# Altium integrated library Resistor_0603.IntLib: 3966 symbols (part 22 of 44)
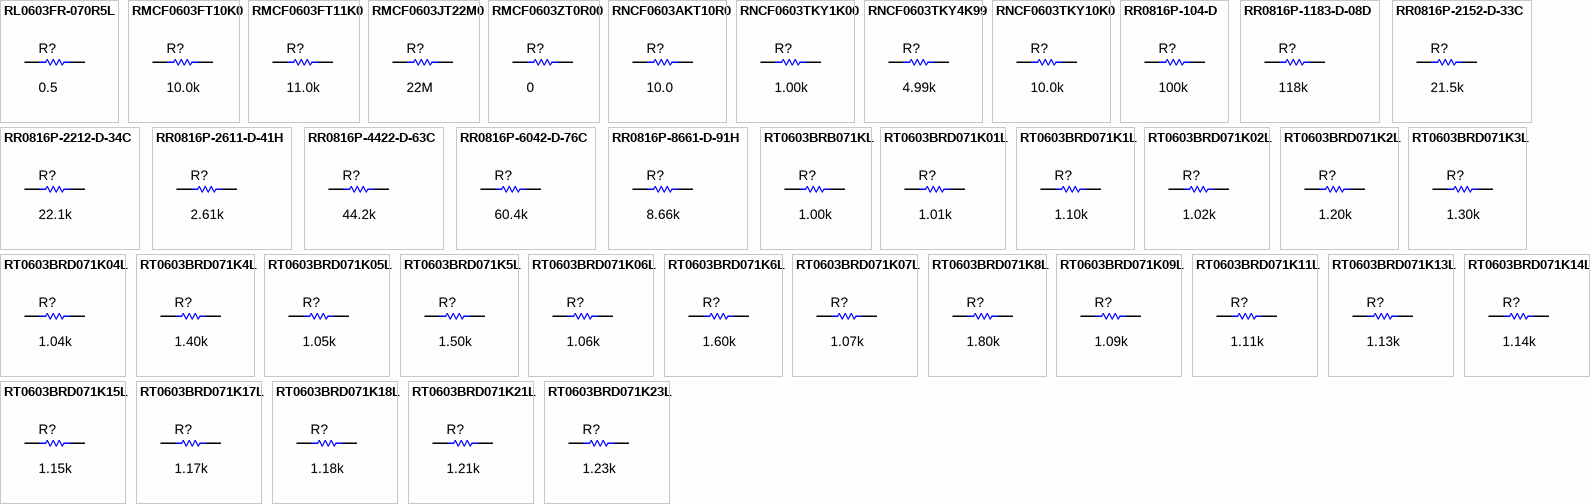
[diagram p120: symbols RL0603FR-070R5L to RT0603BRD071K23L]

## RR0816P-8661-D-91H
designator R?  ValueDisplayed: 8.66k  (hidden comment: RR0816P-8661-D-91H)
RES, 8.66 k, 0.5%, 0.0625 W, 0603; Manufacturer: Susumu Co Ltd; CompType: Resistor; Value: 8.66k; Res_ohm: 8660; Value_Code: 8k66; Tolerance_%: 0.5; Power_W: 0.0625; VDC_V: 75; TempCo: 25 ppm/C; SizeArea_mm2: 1.3175; SizeX_mm: 1.55; SizeY_mm: 0.85; EIA_Code: E192; U/M: EA; AEC Category: Q200; AEC Qualified: N
signal-integrity model Resistor
simulation model Resistor
footprint 0603_HR
pins: 1, 2

## RT0603BRB071KL
designator R?  ValueDisplayed: 1.00k  (hidden comment: RT0603BRB071KL)
RES, 1.00 k, 0.1%, 0.1 W, 0603; Manufacturer: Yageo America; CompType: Resistor; Value: 1.00k; Res_ohm: 1000; Value_Code: 1k00; Tolerance_%: 0.1; Value2: 0.1W; VDC_V: 75; TempCo: 10 ppm/C; SizeArea_mm2: 1.28; SizeX_mm: 1.6; SizeY_mm: 0.8; SizeZ_mm: 1; EIA_Code: E192; U/M: EA; AEC Category: Q200; AEC Qualified: N; Green_Lifecycle: Active; Green_REACh: Passed
signal-integrity model Resistor
simulation model Resistor
footprint 0603
footprint 0603M
footprint 0603L
footprint 0603_HV
footprint 0603S
pins: 1, 2

## RT0603BRD071K01L
designator R?  ValueDisplayed: 1.01k  (hidden comment: RT0603BRD071K01L)
RES, 1.01 k, 0.1%, 0.1 W, 0603; Manufacturer: Yageo America; CompType: Resistor; Value: 1.01k; Res_ohm: 1010; Value_Code: 1k01; Tolerance_%: 0.1; Value2: 0.1W; VDC_V: 75; TempCo: 25 ppm/C; SizeArea_mm2: 1.28; SizeX_mm: 1.6; SizeY_mm: 0.8; SizeZ_mm: 1; EIA_Code: E192; U/M: EA; AEC Category: Q200
signal-integrity model Resistor
simulation model Resistor
footprint 0603
footprint 0603M
footprint 0603L
footprint 0603_HV
footprint 0603S
pins: 1, 2

## RT0603BRD071K1L
designator R?  ValueDisplayed: 1.10k  (hidden comment: RT0603BRD071K1L)
RES, 1.10 k, 0.1%, 0.1 W, 0603; Manufacturer: Yageo America; CompType: Resistor; Value: 1.10k; Res_ohm: 1100; Value_Code: 1k10; Tolerance_%: 0.1; Value2: 0.1W; VDC_V: 75; TempCo: 25 ppm/C; SizeArea_mm2: 1.28; SizeX_mm: 1.6; SizeY_mm: 0.8; SizeZ_mm: 1; EIA_Code: E192; U/M: EA; AEC Category: Q200
signal-integrity model Resistor
simulation model Resistor
footprint 0603
footprint 0603M
footprint 0603L
footprint 0603_HV
footprint 0603S
pins: 1, 2

## RT0603BRD071K02L
designator R?  ValueDisplayed: 1.02k  (hidden comment: RT0603BRD071K02L)
RES, 1.02 k, 0.1%, 0.1 W, 0603; Manufacturer: Yageo America; CompType: Resistor; Value: 1.02k; Res_ohm: 1020; Value_Code: 1k02; Tolerance_%: 0.1; Value2: 0.1W; VDC_V: 75; TempCo: 25 ppm/C; SizeArea_mm2: 1.28; SizeX_mm: 1.6; SizeY_mm: 0.8; SizeZ_mm: 1; EIA_Code: E192; U/M: EA; AEC Category: Q200
signal-integrity model Resistor
simulation model Resistor
footprint 0603
footprint 0603M
footprint 0603L
footprint 0603_HV
footprint 0603S
pins: 1, 2

## RT0603BRD071K2L
designator R?  ValueDisplayed: 1.20k  (hidden comment: RT0603BRD071K2L)
RES, 1.20 k, 0.1%, 0.1 W, 0603; Manufacturer: Yageo America; CompType: Resistor; Value: 1.20k; Res_ohm: 1200; Value_Code: 1k20; Tolerance_%: 0.1; Value2: 0.1W; VDC_V: 75; TempCo: 25 ppm/C; SizeArea_mm2: 1.28; SizeX_mm: 1.6; SizeY_mm: 0.8; SizeZ_mm: 1; EIA_Code: E192; U/M: EA; AEC Category: Q200; Green_Lifecycle: Active; Green_REACh: Passed
signal-integrity model Resistor
simulation model Resistor
footprint 0603
footprint 0603M
footprint 0603L
footprint 0603_HV
footprint 0603S
pins: 1, 2

## RT0603BRD071K3L
designator R?  ValueDisplayed: 1.30k  (hidden comment: RT0603BRD071K3L)
RES, 1.30 k, 0.1%, 0.1 W, 0603; Manufacturer: Yageo America; CompType: Resistor; Value: 1.30k; Res_ohm: 1300; Value_Code: 1k30; Tolerance_%: 0.1; Value2: 0.1W; VDC_V: 75; TempCo: 25 ppm/C; SizeArea_mm2: 1.28; SizeX_mm: 1.6; SizeY_mm: 0.8; SizeZ_mm: 1; EIA_Code: E192; U/M: EA; AEC Category: Q200
signal-integrity model Resistor
simulation model Resistor
footprint 0603
footprint 0603M
footprint 0603L
footprint 0603_HV
footprint 0603S
pins: 1, 2

## RT0603BRD071K04L
designator R?  ValueDisplayed: 1.04k  (hidden comment: RT0603BRD071K04L)
RES, 1.04 k, 0.1%, 0.1 W, 0603; Manufacturer: Yageo America; CompType: Resistor; Value: 1.04k; Res_ohm: 1040; Value_Code: 1k04; Tolerance_%: 0.1; Value2: 0.1W; VDC_V: 75; TempCo: 25 ppm/C; SizeArea_mm2: 1.28; SizeX_mm: 1.6; SizeY_mm: 0.8; SizeZ_mm: 1; EIA_Code: E192; U/M: EA; AEC Category: Q200
signal-integrity model Resistor
simulation model Resistor
footprint 0603
footprint 0603M
footprint 0603L
footprint 0603_HV
footprint 0603S
pins: 1, 2

## RT0603BRD071K4L
designator R?  ValueDisplayed: 1.40k  (hidden comment: RT0603BRD071K4L)
RES, 1.40 k, 0.1%, 0.1 W, 0603; Manufacturer: Yageo America; CompType: Resistor; Value: 1.40k; Res_ohm: 1400; Value_Code: 1k40; Tolerance_%: 0.1; Value2: 0.1W; VDC_V: 75; TempCo: 25 ppm/C; SizeArea_mm2: 1.28; SizeX_mm: 1.6; SizeY_mm: 0.8; SizeZ_mm: 1; EIA_Code: E192; U/M: EA; AEC Category: Q200
signal-integrity model Resistor
simulation model Resistor
footprint 0603
footprint 0603M
footprint 0603L
footprint 0603_HV
footprint 0603S
pins: 1, 2

## RT0603BRD071K05L
designator R?  ValueDisplayed: 1.05k  (hidden comment: RT0603BRD071K05L)
RES, 1.05 k, 0.1%, 0.1 W, 0603; Manufacturer: Yageo America; CompType: Resistor; Value: 1.05k; Res_ohm: 1050; Value_Code: 1k05; Tolerance_%: 0.1; Value2: 0.1W; VDC_V: 75; TempCo: 25 ppm/C; SizeArea_mm2: 1.28; SizeX_mm: 1.6; SizeY_mm: 0.8; SizeZ_mm: 1; EIA_Code: E192; U/M: EA; AEC Category: Q200
signal-integrity model Resistor
simulation model Resistor
footprint 0603
footprint 0603M
footprint 0603L
footprint 0603_HV
footprint 0603S
pins: 1, 2

## RT0603BRD071K5L
designator R?  ValueDisplayed: 1.50k  (hidden comment: RT0603BRD071K5L)
RES, 1.50 k, 0.1%, 0.1 W, 0603; Manufacturer: Yageo America; CompType: Resistor; Value: 1.50k; Res_ohm: 1500; Value_Code: 1k50; Tolerance_%: 0.1; Value2: 0.1W; VDC_V: 75; TempCo: 25 ppm/C; SizeArea_mm2: 1.28; SizeX_mm: 1.6; SizeY_mm: 0.8; SizeZ_mm: 1; EIA_Code: E192; U/M: EA; AEC Category: Q200
signal-integrity model Resistor
simulation model Resistor
footprint 0603
footprint 0603M
footprint 0603L
footprint 0603_HV
footprint 0603S
pins: 1, 2

## RT0603BRD071K06L
designator R?  ValueDisplayed: 1.06k  (hidden comment: RT0603BRD071K06L)
RES, 1.06 k, 0.1%, 0.1 W, 0603; Manufacturer: Yageo America; CompType: Resistor; Value: 1.06k; Res_ohm: 1060; Value_Code: 1k06; Tolerance_%: 0.1; Value2: 0.1W; VDC_V: 75; TempCo: 25 ppm/C; SizeArea_mm2: 1.28; SizeX_mm: 1.6; SizeY_mm: 0.8; SizeZ_mm: 1; EIA_Code: E192; U/M: EA; AEC Category: Q200
signal-integrity model Resistor
simulation model Resistor
footprint 0603
footprint 0603M
footprint 0603L
footprint 0603_HV
footprint 0603S
pins: 1, 2

## RT0603BRD071K6L
designator R?  ValueDisplayed: 1.60k  (hidden comment: RT0603BRD071K6L)
RES, 1.60 k, 0.1%, 0.1 W, 0603; Manufacturer: Yageo America; CompType: Resistor; Value: 1.60k; Res_ohm: 1600; Value_Code: 1k60; Tolerance_%: 0.1; Value2: 0.1W; VDC_V: 75; TempCo: 25 ppm/C; SizeArea_mm2: 1.28; SizeX_mm: 1.6; SizeY_mm: 0.8; SizeZ_mm: 1; EIA_Code: E192; U/M: EA; AEC Category: Q200
signal-integrity model Resistor
simulation model Resistor
footprint 0603
footprint 0603M
footprint 0603L
footprint 0603_HV
footprint 0603S
pins: 1, 2

## RT0603BRD071K07L
designator R?  ValueDisplayed: 1.07k  (hidden comment: RT0603BRD071K07L)
RES, 1.07 k, 0.1%, 0.1 W, 0603; Manufacturer: Yageo America; CompType: Resistor; Value: 1.07k; Res_ohm: 1070; Value_Code: 1k07; Tolerance_%: 0.1; Value2: 0.1W; VDC_V: 75; TempCo: 25 ppm/C; SizeArea_mm2: 1.28; SizeX_mm: 1.6; SizeY_mm: 0.8; SizeZ_mm: 1; EIA_Code: E192; U/M: EA; AEC Category: Q200
signal-integrity model Resistor
simulation model Resistor
footprint 0603
footprint 0603M
footprint 0603L
footprint 0603_HV
footprint 0603S
pins: 1, 2

## RT0603BRD071K8L
designator R?  ValueDisplayed: 1.80k  (hidden comment: RT0603BRD071K8L)
RES, 1.80 k, 0.1%, 0.1 W, 0603; Manufacturer: Yageo America; CompType: Resistor; Value: 1.80k; Res_ohm: 1800; Value_Code: 1k80; Tolerance_%: 0.1; Value2: 0.1W; VDC_V: 75; TempCo: 25 ppm/C; SizeArea_mm2: 1.28; SizeX_mm: 1.6; SizeY_mm: 0.8; SizeZ_mm: 1; EIA_Code: E192; U/M: EA; AEC Category: Q200; Green_Lifecycle: Active; Green_REACh: Passed
signal-integrity model Resistor
simulation model Resistor
footprint 0603
footprint 0603M
footprint 0603L
footprint 0603_HV
footprint 0603S
pins: 1, 2

## RT0603BRD071K09L
designator R?  ValueDisplayed: 1.09k  (hidden comment: RT0603BRD071K09L)
RES, 1.09 k, 0.1%, 0.1 W, 0603; Manufacturer: Yageo America; CompType: Resistor; Value: 1.09k; Res_ohm: 1090; Value_Code: 1k09; Tolerance_%: 0.1; Value2: 0.1W; VDC_V: 75; TempCo: 25 ppm/C; SizeArea_mm2: 1.28; SizeX_mm: 1.6; SizeY_mm: 0.8; SizeZ_mm: 1; EIA_Code: E192; U/M: EA; AEC Category: Q200
signal-integrity model Resistor
simulation model Resistor
footprint 0603
footprint 0603M
footprint 0603L
footprint 0603_HV
footprint 0603S
pins: 1, 2

## RT0603BRD071K11L
designator R?  ValueDisplayed: 1.11k  (hidden comment: RT0603BRD071K11L)
RES, 1.11 k, 0.1%, 0.1 W, 0603; Manufacturer: Yageo America; CompType: Resistor; Value: 1.11k; Res_ohm: 1110; Value_Code: 1k11; Tolerance_%: 0.1; Value2: 0.1W; VDC_V: 75; TempCo: 25 ppm/C; SizeArea_mm2: 1.28; SizeX_mm: 1.6; SizeY_mm: 0.8; SizeZ_mm: 1; EIA_Code: E192; U/M: EA; AEC Category: Q200
signal-integrity model Resistor
simulation model Resistor
footprint 0603
footprint 0603M
footprint 0603L
footprint 0603_HV
footprint 0603S
pins: 1, 2

## RT0603BRD071K13L
designator R?  ValueDisplayed: 1.13k  (hidden comment: RT0603BRD071K13L)
RES, 1.13 k, 0.1%, 0.1 W, 0603; Manufacturer: Yageo America; CompType: Resistor; Value: 1.13k; Res_ohm: 1130; Value_Code: 1k13; Tolerance_%: 0.1; Value2: 0.1W; VDC_V: 75; TempCo: 25 ppm/C; SizeArea_mm2: 1.28; SizeX_mm: 1.6; SizeY_mm: 0.8; SizeZ_mm: 1; EIA_Code: E192; U/M: EA; AEC Category: Q200
signal-integrity model Resistor
simulation model Resistor
footprint 0603
footprint 0603M
footprint 0603L
footprint 0603_HV
footprint 0603S
pins: 1, 2

## RT0603BRD071K14L
designator R?  ValueDisplayed: 1.14k  (hidden comment: RT0603BRD071K14L)
RES, 1.14 k, 0.1%, 0.1 W, 0603; Manufacturer: Yageo America; CompType: Resistor; Value: 1.14k; Res_ohm: 1140; Value_Code: 1k14; Tolerance_%: 0.1; Value2: 0.1W; VDC_V: 75; TempCo: 25 ppm/C; SizeArea_mm2: 1.28; SizeX_mm: 1.6; SizeY_mm: 0.8; SizeZ_mm: 1; EIA_Code: E192; U/M: EA; AEC Category: Q200
signal-integrity model Resistor
simulation model Resistor
footprint 0603
footprint 0603M
footprint 0603L
footprint 0603_HV
footprint 0603S
pins: 1, 2

## RT0603BRD071K15L
designator R?  ValueDisplayed: 1.15k  (hidden comment: RT0603BRD071K15L)
RES, 1.15 k, 0.1%, 0.1 W, 0603; Manufacturer: Yageo America; CompType: Resistor; Value: 1.15k; Res_ohm: 1150; Value_Code: 1k15; Tolerance_%: 0.1; Value2: 0.1W; VDC_V: 75; TempCo: 25 ppm/C; SizeArea_mm2: 1.28; SizeX_mm: 1.6; SizeY_mm: 0.8; SizeZ_mm: 1; EIA_Code: E192; U/M: EA; AEC Category: Q200
signal-integrity model Resistor
simulation model Resistor
footprint 0603
footprint 0603M
footprint 0603L
footprint 0603_HV
footprint 0603S
pins: 1, 2

## RT0603BRD071K17L
designator R?  ValueDisplayed: 1.17k  (hidden comment: RT0603BRD071K17L)
RES, 1.17 k, 0.1%, 0.1 W, 0603; Manufacturer: Yageo America; CompType: Resistor; Value: 1.17k; Res_ohm: 1170; Value_Code: 1k17; Tolerance_%: 0.1; Value2: 0.1W; VDC_V: 75; TempCo: 25 ppm/C; SizeArea_mm2: 1.28; SizeX_mm: 1.6; SizeY_mm: 0.8; SizeZ_mm: 1; EIA_Code: E192; U/M: EA; AEC Category: Q200
signal-integrity model Resistor
simulation model Resistor
footprint 0603
footprint 0603M
footprint 0603L
footprint 0603_HV
footprint 0603S
pins: 1, 2

## RT0603BRD071K18L
designator R?  ValueDisplayed: 1.18k  (hidden comment: RT0603BRD071K18L)
RES, 1.18 k, 0.1%, 0.1 W, 0603; Manufacturer: Yageo America; CompType: Resistor; Value: 1.18k; Res_ohm: 1180; Value_Code: 1k18; Tolerance_%: 0.1; Value2: 0.1W; VDC_V: 75; TempCo: 25 ppm/C; SizeArea_mm2: 1.28; SizeX_mm: 1.6; SizeY_mm: 0.8; SizeZ_mm: 1; EIA_Code: E192; U/M: EA; AEC Category: Q200
signal-integrity model Resistor
simulation model Resistor
footprint 0603
footprint 0603M
footprint 0603L
footprint 0603_HV
footprint 0603S
pins: 1, 2

## RT0603BRD071K21L
designator R?  ValueDisplayed: 1.21k  (hidden comment: RT0603BRD071K21L)
RES, 1.21 k, 0.1%, 0.1 W, 0603; Manufacturer: Yageo America; CompType: Resistor; Value: 1.21k; Res_ohm: 1210; Value_Code: 1k21; Tolerance_%: 0.1; Value2: 0.1W; VDC_V: 75; TempCo: 25 ppm/C; SizeArea_mm2: 1.28; SizeX_mm: 1.6; SizeY_mm: 0.8; SizeZ_mm: 1; EIA_Code: E192; U/M: EA; AEC Category: Q200
signal-integrity model Resistor
simulation model Resistor
footprint 0603
footprint 0603M
footprint 0603L
footprint 0603_HV
footprint 0603S
pins: 1, 2

## RT0603BRD071K23L
designator R?  ValueDisplayed: 1.23k  (hidden comment: RT0603BRD071K23L)
RES, 1.23 k, 0.1%, 0.1 W, 0603; Manufacturer: Yageo America; CompType: Resistor; Value: 1.23k; Res_ohm: 1230; Value_Code: 1k23; Tolerance_%: 0.1; Value2: 0.1W; VDC_V: 75; TempCo: 25 ppm/C; SizeArea_mm2: 1.28; SizeX_mm: 1.6; SizeY_mm: 0.8; SizeZ_mm: 1; EIA_Code: E192; U/M: EA; AEC Category: Q200
signal-integrity model Resistor
simulation model Resistor
footprint 0603
footprint 0603M
footprint 0603L
footprint 0603_HV
footprint 0603S
pins: 1, 2

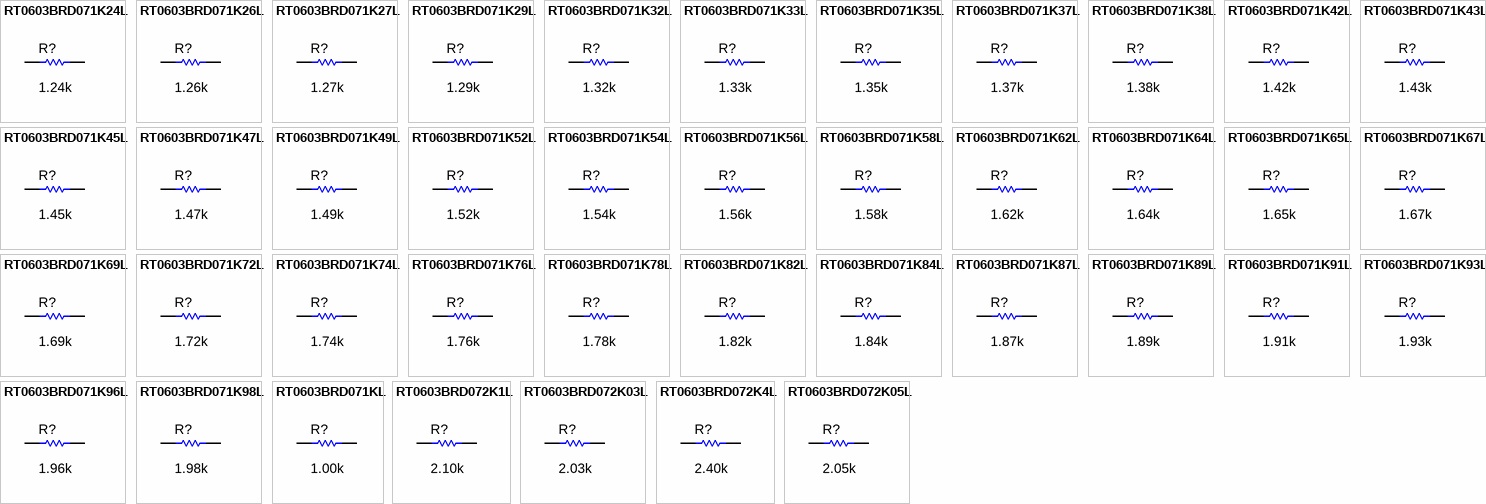
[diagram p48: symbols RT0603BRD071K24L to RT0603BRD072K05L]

## RT0603BRD071K24L
designator R?  ValueDisplayed: 1.24k  (hidden comment: RT0603BRD071K24L)
RES, 1.24 k, 0.1%, 0.1 W, 0603; Manufacturer: Yageo America; CompType: Resistor; Value: 1.24k; Res_ohm: 1240; Value_Code: 1k24; Tolerance_%: 0.1; Value2: 0.1W; VDC_V: 75; TempCo: 25 ppm/C; SizeArea_mm2: 1.28; SizeX_mm: 1.6; SizeY_mm: 0.8; SizeZ_mm: 1; EIA_Code: E192; U/M: EA; AEC Category: Q200
signal-integrity model Resistor
simulation model Resistor
footprint 0603
footprint 0603M
footprint 0603L
footprint 0603_HV
footprint 0603S
pins: 1, 2

## RT0603BRD071K26L
designator R?  ValueDisplayed: 1.26k  (hidden comment: RT0603BRD071K26L)
RES, 1.26 k, 0.1%, 0.1 W, 0603; Manufacturer: Yageo America; CompType: Resistor; Value: 1.26k; Res_ohm: 1260; Value_Code: 1k26; Tolerance_%: 0.1; Value2: 0.1W; VDC_V: 75; TempCo: 25 ppm/C; SizeArea_mm2: 1.28; SizeX_mm: 1.6; SizeY_mm: 0.8; SizeZ_mm: 1; EIA_Code: E192; U/M: EA; AEC Category: Q200
signal-integrity model Resistor
simulation model Resistor
footprint 0603
footprint 0603M
footprint 0603L
footprint 0603_HV
footprint 0603S
pins: 1, 2

## RT0603BRD071K27L
designator R?  ValueDisplayed: 1.27k  (hidden comment: RT0603BRD071K27L)
RES, 1.27 k, 0.1%, 0.1 W, 0603; Manufacturer: Yageo America; CompType: Resistor; Value: 1.27k; Res_ohm: 1270; Value_Code: 1k27; Tolerance_%: 0.1; Value2: 0.1W; VDC_V: 75; TempCo: 25 ppm/C; SizeArea_mm2: 1.28; SizeX_mm: 1.6; SizeY_mm: 0.8; SizeZ_mm: 1; EIA_Code: E192; U/M: EA; AEC Category: Q200
signal-integrity model Resistor
simulation model Resistor
footprint 0603
footprint 0603M
footprint 0603L
footprint 0603_HV
footprint 0603S
pins: 1, 2

## RT0603BRD071K29L
designator R?  ValueDisplayed: 1.29k  (hidden comment: RT0603BRD071K29L)
RES, 1.29 k, 0.1%, 0.1 W, 0603; Manufacturer: Yageo America; CompType: Resistor; Value: 1.29k; Res_ohm: 1290; Value_Code: 1k29; Tolerance_%: 0.1; Value2: 0.1W; VDC_V: 75; TempCo: 25 ppm/C; SizeArea_mm2: 1.28; SizeX_mm: 1.6; SizeY_mm: 0.8; SizeZ_mm: 1; EIA_Code: E192; U/M: EA; AEC Category: Q200
signal-integrity model Resistor
simulation model Resistor
footprint 0603
footprint 0603M
footprint 0603L
footprint 0603_HV
footprint 0603S
pins: 1, 2

## RT0603BRD071K32L
designator R?  ValueDisplayed: 1.32k  (hidden comment: RT0603BRD071K32L)
RES, 1.32 k, 0.1%, 0.1 W, 0603; Manufacturer: Yageo America; CompType: Resistor; Value: 1.32k; Res_ohm: 1320; Value_Code: 1k32; Tolerance_%: 0.1; Value2: 0.1W; VDC_V: 75; TempCo: 25 ppm/C; SizeArea_mm2: 1.28; SizeX_mm: 1.6; SizeY_mm: 0.8; SizeZ_mm: 1; EIA_Code: E192; U/M: EA; AEC Category: Q200
signal-integrity model Resistor
simulation model Resistor
footprint 0603
footprint 0603M
footprint 0603L
footprint 0603_HV
footprint 0603S
pins: 1, 2

## RT0603BRD071K33L
designator R?  ValueDisplayed: 1.33k  (hidden comment: RT0603BRD071K33L)
RES, 1.33 k, 0.1%, 0.1 W, 0603; Manufacturer: Yageo America; CompType: Resistor; Value: 1.33k; Res_ohm: 1330; Value_Code: 1k33; Tolerance_%: 0.1; Value2: 0.1W; VDC_V: 75; TempCo: 25 ppm/C; SizeArea_mm2: 1.28; SizeX_mm: 1.6; SizeY_mm: 0.8; SizeZ_mm: 1; EIA_Code: E192; U/M: EA; AEC Category: Q200
signal-integrity model Resistor
simulation model Resistor
footprint 0603
footprint 0603M
footprint 0603L
footprint 0603_HV
footprint 0603S
pins: 1, 2

## RT0603BRD071K35L
designator R?  ValueDisplayed: 1.35k  (hidden comment: RT0603BRD071K35L)
RES, 1.35 k, 0.1%, 0.1 W, 0603; Manufacturer: Yageo America; CompType: Resistor; Value: 1.35k; Res_ohm: 1350; Value_Code: 1k35; Tolerance_%: 0.1; Value2: 0.1W; VDC_V: 75; TempCo: 25 ppm/C; SizeArea_mm2: 1.28; SizeX_mm: 1.6; SizeY_mm: 0.8; SizeZ_mm: 1; EIA_Code: E192; U/M: EA; AEC Category: Q200
signal-integrity model Resistor
simulation model Resistor
footprint 0603
footprint 0603M
footprint 0603L
footprint 0603_HV
footprint 0603S
pins: 1, 2

## RT0603BRD071K37L
designator R?  ValueDisplayed: 1.37k  (hidden comment: RT0603BRD071K37L)
RES, 1.37 k, 0.1%, 0.1 W, 0603; Manufacturer: Yageo America; CompType: Resistor; Value: 1.37k; Res_ohm: 1370; Value_Code: 1k37; Tolerance_%: 0.1; Value2: 0.1W; VDC_V: 75; TempCo: 25 ppm/C; SizeArea_mm2: 1.28; SizeX_mm: 1.6; SizeY_mm: 0.8; SizeZ_mm: 1; EIA_Code: E192; U/M: EA; AEC Category: Q200
signal-integrity model Resistor
simulation model Resistor
footprint 0603
footprint 0603M
footprint 0603L
footprint 0603_HV
footprint 0603S
pins: 1, 2

## RT0603BRD071K38L
designator R?  ValueDisplayed: 1.38k  (hidden comment: RT0603BRD071K38L)
RES, 1.38 k, 0.1%, 0.1 W, 0603; Manufacturer: Yageo America; CompType: Resistor; Value: 1.38k; Res_ohm: 1380; Value_Code: 1k38; Tolerance_%: 0.1; Value2: 0.1W; VDC_V: 75; TempCo: 25 ppm/C; SizeArea_mm2: 1.28; SizeX_mm: 1.6; SizeY_mm: 0.8; SizeZ_mm: 1; EIA_Code: E192; U/M: EA; AEC Category: Q200
signal-integrity model Resistor
simulation model Resistor
footprint 0603
footprint 0603M
footprint 0603L
footprint 0603_HV
footprint 0603S
pins: 1, 2

## RT0603BRD071K42L
designator R?  ValueDisplayed: 1.42k  (hidden comment: RT0603BRD071K42L)
RES, 1.42 k, 0.1%, 0.1 W, 0603; Manufacturer: Yageo America; CompType: Resistor; Value: 1.42k; Res_ohm: 1420; Value_Code: 1k42; Tolerance_%: 0.1; Value2: 0.1W; VDC_V: 75; TempCo: 25 ppm/C; SizeArea_mm2: 1.28; SizeX_mm: 1.6; SizeY_mm: 0.8; SizeZ_mm: 1; EIA_Code: E192; U/M: EA; AEC Category: Q200
signal-integrity model Resistor
simulation model Resistor
footprint 0603
footprint 0603M
footprint 0603L
footprint 0603_HV
footprint 0603S
pins: 1, 2

## RT0603BRD071K43L
designator R?  ValueDisplayed: 1.43k  (hidden comment: RT0603BRD071K43L)
RES, 1.43 k, 0.1%, 0.1 W, 0603; Manufacturer: Yageo America; CompType: Resistor; Value: 1.43k; Res_ohm: 1430; Value_Code: 1k43; Tolerance_%: 0.1; Value2: 0.1W; VDC_V: 75; TempCo: 25 ppm/C; SizeArea_mm2: 1.28; SizeX_mm: 1.6; SizeY_mm: 0.8; SizeZ_mm: 1; EIA_Code: E192; U/M: EA; AEC Category: Q200
signal-integrity model Resistor
simulation model Resistor
footprint 0603
footprint 0603M
footprint 0603L
footprint 0603_HV
footprint 0603S
pins: 1, 2

## RT0603BRD071K45L
designator R?  ValueDisplayed: 1.45k  (hidden comment: RT0603BRD071K45L)
RES, 1.45 k, 0.1%, 0.1 W, 0603; Manufacturer: Yageo America; CompType: Resistor; Value: 1.45k; Res_ohm: 1450; Value_Code: 1k45; Tolerance_%: 0.1; Value2: 0.1W; VDC_V: 75; TempCo: 25 ppm/C; SizeArea_mm2: 1.28; SizeX_mm: 1.6; SizeY_mm: 0.8; SizeZ_mm: 1; EIA_Code: E192; U/M: EA; AEC Category: Q200
signal-integrity model Resistor
simulation model Resistor
footprint 0603
footprint 0603M
footprint 0603L
footprint 0603_HV
footprint 0603S
pins: 1, 2

## RT0603BRD071K47L
designator R?  ValueDisplayed: 1.47k  (hidden comment: RT0603BRD071K47L)
RES, 1.47 k, 0.1%, 0.1 W, 0603; Manufacturer: Yageo America; CompType: Resistor; Value: 1.47k; Res_ohm: 1470; Value_Code: 1k47; Tolerance_%: 0.1; Value2: 0.1W; VDC_V: 75; TempCo: 25 ppm/C; SizeArea_mm2: 1.28; SizeX_mm: 1.6; SizeY_mm: 0.8; SizeZ_mm: 1; EIA_Code: E192; U/M: EA; AEC Category: Q200
signal-integrity model Resistor
simulation model Resistor
footprint 0603
footprint 0603M
footprint 0603L
footprint 0603_HV
footprint 0603S
pins: 1, 2

## RT0603BRD071K49L
designator R?  ValueDisplayed: 1.49k  (hidden comment: RT0603BRD071K49L)
RES, 1.49 k, 0.1%, 0.1 W, 0603; Manufacturer: Yageo America; CompType: Resistor; Value: 1.49k; Res_ohm: 1490; Value_Code: 1k49; Tolerance_%: 0.1; Value2: 0.1W; VDC_V: 75; TempCo: 25 ppm/C; SizeArea_mm2: 1.28; SizeX_mm: 1.6; SizeY_mm: 0.8; SizeZ_mm: 1; EIA_Code: E192; U/M: EA; AEC Category: Q200
signal-integrity model Resistor
simulation model Resistor
footprint 0603
footprint 0603M
footprint 0603L
footprint 0603_HV
footprint 0603S
pins: 1, 2

## RT0603BRD071K52L
designator R?  ValueDisplayed: 1.52k  (hidden comment: RT0603BRD071K52L)
RES, 1.52 k, 0.1%, 0.1 W, 0603; Manufacturer: Yageo America; CompType: Resistor; Value: 1.52k; Res_ohm: 1520; Value_Code: 1k52; Tolerance_%: 0.1; Value2: 0.1W; VDC_V: 75; TempCo: 25 ppm/C; SizeArea_mm2: 1.28; SizeX_mm: 1.6; SizeY_mm: 0.8; SizeZ_mm: 1; EIA_Code: E192; U/M: EA; AEC Category: Q200
signal-integrity model Resistor
simulation model Resistor
footprint 0603
footprint 0603M
footprint 0603L
footprint 0603_HV
footprint 0603S
pins: 1, 2

## RT0603BRD071K54L
designator R?  ValueDisplayed: 1.54k  (hidden comment: RT0603BRD071K54L)
RES, 1.54 k, 0.1%, 0.1 W, 0603; Manufacturer: Yageo America; CompType: Resistor; Value: 1.54k; Res_ohm: 1540; Value_Code: 1k54; Tolerance_%: 0.1; Value2: 0.1W; VDC_V: 75; TempCo: 25 ppm/C; SizeArea_mm2: 1.28; SizeX_mm: 1.6; SizeY_mm: 0.8; SizeZ_mm: 1; EIA_Code: E192; U/M: EA; AEC Category: Q200
signal-integrity model Resistor
simulation model Resistor
footprint 0603
footprint 0603M
footprint 0603L
footprint 0603_HV
footprint 0603S
pins: 1, 2

## RT0603BRD071K56L
designator R?  ValueDisplayed: 1.56k  (hidden comment: RT0603BRD071K56L)
RES, 1.56 k, 0.1%, 0.1 W, 0603; Manufacturer: Yageo America; CompType: Resistor; Value: 1.56k; Res_ohm: 1560; Value_Code: 1k56; Tolerance_%: 0.1; Value2: 0.1W; VDC_V: 75; TempCo: 25 ppm/C; SizeArea_mm2: 1.28; SizeX_mm: 1.6; SizeY_mm: 0.8; SizeZ_mm: 1; EIA_Code: E192; U/M: EA; AEC Category: Q200
signal-integrity model Resistor
simulation model Resistor
footprint 0603
footprint 0603M
footprint 0603L
footprint 0603_HV
footprint 0603S
pins: 1, 2

## RT0603BRD071K58L
designator R?  ValueDisplayed: 1.58k  (hidden comment: RT0603BRD071K58L)
RES, 1.58 k, 0.1%, 0.1 W, 0603; Manufacturer: Yageo America; CompType: Resistor; Value: 1.58k; Res_ohm: 1580; Value_Code: 1k58; Tolerance_%: 0.1; Value2: 0.1W; VDC_V: 75; TempCo: 25 ppm/C; SizeArea_mm2: 1.28; SizeX_mm: 1.6; SizeY_mm: 0.8; SizeZ_mm: 1; EIA_Code: E192; U/M: EA; AEC Category: Q200
signal-integrity model Resistor
simulation model Resistor
footprint 0603
footprint 0603M
footprint 0603L
footprint 0603_HV
footprint 0603S
pins: 1, 2

## RT0603BRD071K62L
designator R?  ValueDisplayed: 1.62k  (hidden comment: RT0603BRD071K62L)
RES, 1.62 k, 0.1%, 0.1 W, 0603; Manufacturer: Yageo America; CompType: Resistor; Value: 1.62k; Res_ohm: 1620; Value_Code: 1k62; Tolerance_%: 0.1; Value2: 0.1W; VDC_V: 75; TempCo: 25 ppm/C; SizeArea_mm2: 1.28; SizeX_mm: 1.6; SizeY_mm: 0.8; SizeZ_mm: 1; EIA_Code: E192; U/M: EA; AEC Category: Q200
signal-integrity model Resistor
simulation model Resistor
footprint 0603
footprint 0603M
footprint 0603L
footprint 0603_HV
footprint 0603S
pins: 1, 2

## RT0603BRD071K64L
designator R?  ValueDisplayed: 1.64k  (hidden comment: RT0603BRD071K64L)
RES, 1.64 k, 0.1%, 0.1 W, 0603; Manufacturer: Yageo America; CompType: Resistor; Value: 1.64k; Res_ohm: 1640; Value_Code: 1k64; Tolerance_%: 0.1; Value2: 0.1W; VDC_V: 75; TempCo: 25 ppm/C; SizeArea_mm2: 1.28; SizeX_mm: 1.6; SizeY_mm: 0.8; SizeZ_mm: 1; EIA_Code: E192; U/M: EA; AEC Category: Q200
signal-integrity model Resistor
simulation model Resistor
footprint 0603
footprint 0603M
footprint 0603L
footprint 0603_HV
footprint 0603S
pins: 1, 2

## RT0603BRD071K65L
designator R?  ValueDisplayed: 1.65k  (hidden comment: RT0603BRD071K65L)
RES, 1.65 k, 0.1%, 0.1 W, 0603; Manufacturer: Yageo America; CompType: Resistor; Value: 1.65k; Res_ohm: 1650; Value_Code: 1k65; Tolerance_%: 0.1; Value2: 0.1W; VDC_V: 75; TempCo: 25 ppm/C; SizeArea_mm2: 1.28; SizeX_mm: 1.6; SizeY_mm: 0.8; SizeZ_mm: 1; EIA_Code: E192; U/M: EA; AEC Category: Q200
signal-integrity model Resistor
simulation model Resistor
footprint 0603
footprint 0603M
footprint 0603L
footprint 0603_HV
footprint 0603S
pins: 1, 2

## RT0603BRD071K67L
designator R?  ValueDisplayed: 1.67k  (hidden comment: RT0603BRD071K67L)
RES, 1.67 k, 0.1%, 0.1 W, 0603; Manufacturer: Yageo America; CompType: Resistor; Value: 1.67k; Res_ohm: 1670; Value_Code: 1k67; Tolerance_%: 0.1; Value2: 0.1W; VDC_V: 75; TempCo: 25 ppm/C; SizeArea_mm2: 1.28; SizeX_mm: 1.6; SizeY_mm: 0.8; SizeZ_mm: 1; EIA_Code: E192; U/M: EA; AEC Category: Q200
signal-integrity model Resistor
simulation model Resistor
footprint 0603
footprint 0603M
footprint 0603L
footprint 0603_HV
footprint 0603S
pins: 1, 2

## RT0603BRD071K69L
designator R?  ValueDisplayed: 1.69k  (hidden comment: RT0603BRD071K69L)
RES, 1.69 k, 0.1%, 0.1 W, 0603; Manufacturer: Yageo America; CompType: Resistor; Value: 1.69k; Res_ohm: 1690; Value_Code: 1k69; Tolerance_%: 0.1; Value2: 0.1W; VDC_V: 75; TempCo: 25 ppm/C; SizeArea_mm2: 1.28; SizeX_mm: 1.6; SizeY_mm: 0.8; SizeZ_mm: 1; EIA_Code: E192; U/M: EA; AEC Category: Q200
signal-integrity model Resistor
simulation model Resistor
footprint 0603
footprint 0603M
footprint 0603L
footprint 0603_HV
footprint 0603S
pins: 1, 2

## RT0603BRD071K72L
designator R?  ValueDisplayed: 1.72k  (hidden comment: RT0603BRD071K72L)
RES, 1.72 k, 0.1%, 0.1 W, 0603; Manufacturer: Yageo America; CompType: Resistor; Value: 1.72k; Res_ohm: 1720; Value_Code: 1k72; Tolerance_%: 0.1; Value2: 0.1W; VDC_V: 75; TempCo: 25 ppm/C; SizeArea_mm2: 1.28; SizeX_mm: 1.6; SizeY_mm: 0.8; SizeZ_mm: 1; EIA_Code: E192; U/M: EA; AEC Category: Q200
signal-integrity model Resistor
simulation model Resistor
footprint 0603
footprint 0603M
footprint 0603L
footprint 0603_HV
footprint 0603S
pins: 1, 2

## RT0603BRD071K74L
designator R?  ValueDisplayed: 1.74k  (hidden comment: RT0603BRD071K74L)
RES, 1.74 k, 0.1%, 0.1 W, 0603; Manufacturer: Yageo America; CompType: Resistor; Value: 1.74k; Res_ohm: 1740; Value_Code: 1k74; Tolerance_%: 0.1; Value2: 0.1W; VDC_V: 75; TempCo: 25 ppm/C; SizeArea_mm2: 1.28; SizeX_mm: 1.6; SizeY_mm: 0.8; SizeZ_mm: 1; EIA_Code: E192; U/M: EA; AEC Category: Q200
signal-integrity model Resistor
simulation model Resistor
footprint 0603
footprint 0603M
footprint 0603L
footprint 0603_HV
footprint 0603S
pins: 1, 2

## RT0603BRD071K76L
designator R?  ValueDisplayed: 1.76k  (hidden comment: RT0603BRD071K76L)
RES, 1.76 k, 0.1%, 0.1 W, 0603; Manufacturer: Yageo America; CompType: Resistor; Value: 1.76k; Res_ohm: 1760; Value_Code: 1k76; Tolerance_%: 0.1; Value2: 0.1W; VDC_V: 75; TempCo: 25 ppm/C; SizeArea_mm2: 1.28; SizeX_mm: 1.6; SizeY_mm: 0.8; SizeZ_mm: 1; EIA_Code: E192; U/M: EA; AEC Category: Q200
signal-integrity model Resistor
simulation model Resistor
footprint 0603
footprint 0603M
footprint 0603L
footprint 0603_HV
footprint 0603S
pins: 1, 2

## RT0603BRD071K78L
designator R?  ValueDisplayed: 1.78k  (hidden comment: RT0603BRD071K78L)
RES, 1.78 k, 0.1%, 0.1 W, 0603; Manufacturer: Yageo America; CompType: Resistor; Value: 1.78k; Res_ohm: 1780; Value_Code: 1k78; Tolerance_%: 0.1; Value2: 0.1W; VDC_V: 75; TempCo: 25 ppm/C; SizeArea_mm2: 1.28; SizeX_mm: 1.6; SizeY_mm: 0.8; SizeZ_mm: 1; EIA_Code: E192; U/M: EA; AEC Category: Q200
signal-integrity model Resistor
simulation model Resistor
footprint 0603
footprint 0603M
footprint 0603L
footprint 0603_HV
footprint 0603S
pins: 1, 2

## RT0603BRD071K82L
designator R?  ValueDisplayed: 1.82k  (hidden comment: RT0603BRD071K82L)
RES, 1.82 k, 0.1%, 0.1 W, 0603; Manufacturer: Yageo America; CompType: Resistor; Value: 1.82k; Res_ohm: 1820; Value_Code: 1k82; Tolerance_%: 0.1; Value2: 0.1W; VDC_V: 75; TempCo: 25 ppm/C; SizeArea_mm2: 1.28; SizeX_mm: 1.6; SizeY_mm: 0.8; SizeZ_mm: 1; EIA_Code: E192; U/M: EA; AEC Category: Q200
signal-integrity model Resistor
simulation model Resistor
footprint 0603
footprint 0603M
footprint 0603L
footprint 0603_HV
footprint 0603S
pins: 1, 2

## RT0603BRD071K84L
designator R?  ValueDisplayed: 1.84k  (hidden comment: RT0603BRD071K84L)
RES, 1.84 k, 0.1%, 0.1 W, 0603; Manufacturer: Yageo America; CompType: Resistor; Value: 1.84k; Res_ohm: 1840; Value_Code: 1k84; Tolerance_%: 0.1; Value2: 0.1W; VDC_V: 75; TempCo: 25 ppm/C; SizeArea_mm2: 1.28; SizeX_mm: 1.6; SizeY_mm: 0.8; SizeZ_mm: 1; EIA_Code: E192; U/M: EA; AEC Category: Q200
signal-integrity model Resistor
simulation model Resistor
footprint 0603
footprint 0603M
footprint 0603L
footprint 0603_HV
footprint 0603S
pins: 1, 2

## RT0603BRD071K87L
designator R?  ValueDisplayed: 1.87k  (hidden comment: RT0603BRD071K87L)
RES, 1.87 k, 0.1%, 0.1 W, 0603; Manufacturer: Yageo America; CompType: Resistor; Value: 1.87k; Res_ohm: 1870; Value_Code: 1k87; Tolerance_%: 0.1; Value2: 0.1W; VDC_V: 75; TempCo: 25 ppm/C; SizeArea_mm2: 1.28; SizeX_mm: 1.6; SizeY_mm: 0.8; SizeZ_mm: 1; EIA_Code: E192; U/M: EA; AEC Category: Q200
signal-integrity model Resistor
simulation model Resistor
footprint 0603
footprint 0603M
footprint 0603L
footprint 0603_HV
footprint 0603S
pins: 1, 2

## RT0603BRD071K89L
designator R?  ValueDisplayed: 1.89k  (hidden comment: RT0603BRD071K89L)
RES, 1.89 k, 0.1%, 0.1 W, 0603; Manufacturer: Yageo America; CompType: Resistor; Value: 1.89k; Res_ohm: 1890; Value_Code: 1k89; Tolerance_%: 0.1; Value2: 0.1W; VDC_V: 75; TempCo: 25 ppm/C; SizeArea_mm2: 1.28; SizeX_mm: 1.6; SizeY_mm: 0.8; SizeZ_mm: 1; EIA_Code: E192; U/M: EA; AEC Category: Q200
signal-integrity model Resistor
simulation model Resistor
footprint 0603
footprint 0603M
footprint 0603L
footprint 0603_HV
footprint 0603S
pins: 1, 2

## RT0603BRD071K91L
designator R?  ValueDisplayed: 1.91k  (hidden comment: RT0603BRD071K91L)
RES, 1.91 k, 0.1%, 0.1 W, 0603; Manufacturer: Yageo America; CompType: Resistor; Value: 1.91k; Res_ohm: 1910; Value_Code: 1k91; Tolerance_%: 0.1; Value2: 0.1W; VDC_V: 75; TempCo: 25 ppm/C; SizeArea_mm2: 1.28; SizeX_mm: 1.6; SizeY_mm: 0.8; SizeZ_mm: 1; EIA_Code: E192; U/M: EA; AEC Category: Q200
signal-integrity model Resistor
simulation model Resistor
footprint 0603
footprint 0603M
footprint 0603L
footprint 0603_HV
footprint 0603S
pins: 1, 2

## RT0603BRD071K93L
designator R?  ValueDisplayed: 1.93k  (hidden comment: RT0603BRD071K93L)
RES, 1.93 k, 0.1%, 0.1 W, 0603; Manufacturer: Yageo America; CompType: Resistor; Value: 1.93k; Res_ohm: 1930; Value_Code: 1k93; Tolerance_%: 0.1; Value2: 0.1W; VDC_V: 75; TempCo: 25 ppm/C; SizeArea_mm2: 1.28; SizeX_mm: 1.6; SizeY_mm: 0.8; SizeZ_mm: 1; EIA_Code: E192; U/M: EA; AEC Category: Q200
signal-integrity model Resistor
simulation model Resistor
footprint 0603
footprint 0603M
footprint 0603L
footprint 0603_HV
footprint 0603S
pins: 1, 2

## RT0603BRD071K96L
designator R?  ValueDisplayed: 1.96k  (hidden comment: RT0603BRD071K96L)
RES, 1.96 k, 0.1%, 0.1 W, 0603; Manufacturer: Yageo America; CompType: Resistor; Value: 1.96k; Res_ohm: 1960; Value_Code: 1k96; Tolerance_%: 0.1; Value2: 0.1W; VDC_V: 75; TempCo: 25 ppm/C; SizeArea_mm2: 1.28; SizeX_mm: 1.6; SizeY_mm: 0.8; SizeZ_mm: 1; EIA_Code: E192; U/M: EA; AEC Category: Q200
signal-integrity model Resistor
simulation model Resistor
footprint 0603
footprint 0603M
footprint 0603L
footprint 0603_HV
footprint 0603S
pins: 1, 2

## RT0603BRD071K98L
designator R?  ValueDisplayed: 1.98k  (hidden comment: RT0603BRD071K98L)
RES, 1.98 k, 0.1%, 0.1 W, 0603; Manufacturer: Yageo America; CompType: Resistor; Value: 1.98k; Res_ohm: 1980; Value_Code: 1k98; Tolerance_%: 0.1; Value2: 0.1W; VDC_V: 75; TempCo: 25 ppm/C; SizeArea_mm2: 1.28; SizeX_mm: 1.6; SizeY_mm: 0.8; SizeZ_mm: 1; EIA_Code: E192; U/M: EA; AEC Category: Q200
signal-integrity model Resistor
simulation model Resistor
footprint 0603
footprint 0603M
footprint 0603L
footprint 0603_HV
footprint 0603S
pins: 1, 2

## RT0603BRD071KL
designator R?  ValueDisplayed: 1.00k  (hidden comment: RT0603BRD071KL)
RES, 1.00 k, 0.1%, 0.1 W, 0603; Manufacturer: Yageo America; CompType: Resistor; Value: 1.00k; Res_ohm: 1000; Value_Code: 1k00; Tolerance_%: 0.1; Value2: 0.1W; VDC_V: 75; TempCo: 25 ppm/C; SizeArea_mm2: 1.28; SizeX_mm: 1.6; SizeY_mm: 0.8; SizeZ_mm: 1; EIA_Code: E192; U/M: EA; AEC Category: Q200; Green_Lifecycle: Active; Green_REACh: Passed
signal-integrity model Resistor
simulation model Resistor
footprint 0603
footprint 0603M
footprint 0603L
footprint 0603_HV
footprint 0603S
pins: 1, 2

## RT0603BRD072K1L
designator R?  ValueDisplayed: 2.10k  (hidden comment: RT0603BRD072K1L)
RES, 2.10 k, 0.1%, 0.1 W, 0603; Manufacturer: Yageo America; CompType: Resistor; Value: 2.10k; Res_ohm: 2100; Value_Code: 2k10; Tolerance_%: 0.1; Value2: 0.1W; VDC_V: 75; TempCo: 25 ppm/C; SizeArea_mm2: 1.28; SizeX_mm: 1.6; SizeY_mm: 0.8; SizeZ_mm: 1; EIA_Code: E192; U/M: EA; AEC Category: Q200
signal-integrity model Resistor
simulation model Resistor
footprint 0603
footprint 0603M
footprint 0603L
footprint 0603_HV
footprint 0603S
pins: 1, 2

## RT0603BRD072K03L
designator R?  ValueDisplayed: 2.03k  (hidden comment: RT0603BRD072K03L)
RES, 2.03 k, 0.1%, 0.1 W, 0603; Manufacturer: Yageo America; CompType: Resistor; Value: 2.03k; Res_ohm: 2030; Value_Code: 2k03; Tolerance_%: 0.1; Value2: 0.1W; VDC_V: 75; TempCo: 25 ppm/C; SizeArea_mm2: 1.28; SizeX_mm: 1.6; SizeY_mm: 0.8; SizeZ_mm: 1; EIA_Code: E192; U/M: EA; AEC Category: Q200
signal-integrity model Resistor
simulation model Resistor
footprint 0603
footprint 0603M
footprint 0603L
footprint 0603_HV
footprint 0603S
pins: 1, 2

## RT0603BRD072K4L
designator R?  ValueDisplayed: 2.40k  (hidden comment: RT0603BRD072K4L)
RES, 2.40 k, 0.1%, 0.1 W, 0603; Manufacturer: Yageo America; CompType: Resistor; Value: 2.40k; Res_ohm: 2400; Value_Code: 2k40; Tolerance_%: 0.1; Value2: 0.1W; VDC_V: 75; TempCo: 25 ppm/C; SizeArea_mm2: 1.28; SizeX_mm: 1.6; SizeY_mm: 0.8; SizeZ_mm: 1; EIA_Code: E192; U/M: EA; AEC Category: Q200
signal-integrity model Resistor
simulation model Resistor
footprint 0603
footprint 0603M
footprint 0603L
footprint 0603_HV
footprint 0603S
pins: 1, 2

## RT0603BRD072K05L
designator R?  ValueDisplayed: 2.05k  (hidden comment: RT0603BRD072K05L)
RES, 2.05 k, 0.1%, 0.1 W, 0603; Manufacturer: Yageo America; CompType: Resistor; Value: 2.05k; Res_ohm: 2050; Value_Code: 2k05; Tolerance_%: 0.1; Value2: 0.1W; VDC_V: 75; TempCo: 25 ppm/C; SizeArea_mm2: 1.28; SizeX_mm: 1.6; SizeY_mm: 0.8; SizeZ_mm: 1; EIA_Code: E192; U/M: EA; AEC Category: Q200
signal-integrity model Resistor
simulation model Resistor
footprint 0603
footprint 0603M
footprint 0603L
footprint 0603_HV
footprint 0603S
pins: 1, 2

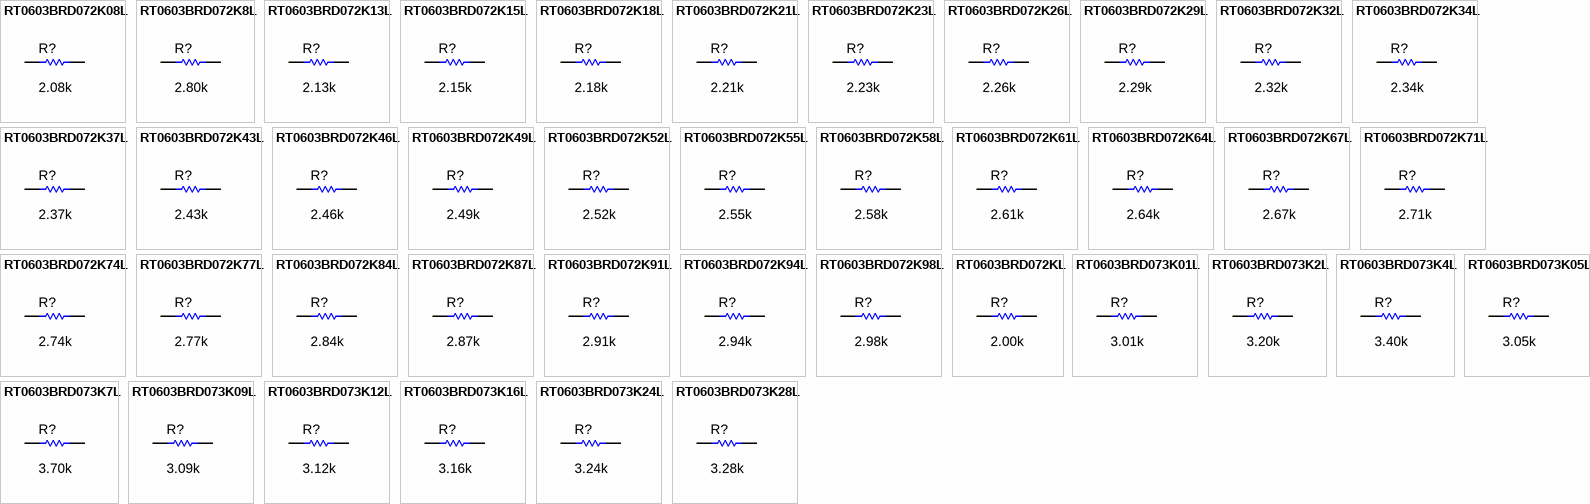
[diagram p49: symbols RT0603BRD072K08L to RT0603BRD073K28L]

## RT0603BRD072K08L
designator R?  ValueDisplayed: 2.08k  (hidden comment: RT0603BRD072K08L)
RES, 2.08 k, 0.1%, 0.1 W, 0603; Manufacturer: Yageo America; CompType: Resistor; Value: 2.08k; Res_ohm: 2080; Value_Code: 2k08; Tolerance_%: 0.1; Value2: 0.1W; VDC_V: 75; TempCo: 25 ppm/C; SizeArea_mm2: 1.28; SizeX_mm: 1.6; SizeY_mm: 0.8; SizeZ_mm: 1; EIA_Code: E192; U/M: EA; AEC Category: Q200
signal-integrity model Resistor
simulation model Resistor
footprint 0603
footprint 0603M
footprint 0603L
footprint 0603_HV
footprint 0603S
pins: 1, 2

## RT0603BRD072K8L
designator R?  ValueDisplayed: 2.80k  (hidden comment: RT0603BRD072K8L)
RES, 2.80 k, 0.1%, 0.1 W, 0603; Manufacturer: Yageo America; CompType: Resistor; Value: 2.80k; Res_ohm: 2800; Value_Code: 2k80; Tolerance_%: 0.1; Value2: 0.1W; VDC_V: 75; TempCo: 25 ppm/C; SizeArea_mm2: 1.28; SizeX_mm: 1.6; SizeY_mm: 0.8; SizeZ_mm: 1; EIA_Code: E192; U/M: EA; AEC Category: Q200
signal-integrity model Resistor
simulation model Resistor
footprint 0603
footprint 0603M
footprint 0603L
footprint 0603_HV
footprint 0603S
pins: 1, 2

## RT0603BRD072K13L
designator R?  ValueDisplayed: 2.13k  (hidden comment: RT0603BRD072K13L)
RES, 2.13 k, 0.1%, 0.1 W, 0603; Manufacturer: Yageo America; CompType: Resistor; Value: 2.13k; Res_ohm: 2130; Value_Code: 2k13; Tolerance_%: 0.1; Value2: 0.1W; VDC_V: 75; TempCo: 25 ppm/C; SizeArea_mm2: 1.28; SizeX_mm: 1.6; SizeY_mm: 0.8; SizeZ_mm: 1; EIA_Code: E192; U/M: EA; AEC Category: Q200
signal-integrity model Resistor
simulation model Resistor
footprint 0603
footprint 0603M
footprint 0603L
footprint 0603_HV
footprint 0603S
pins: 1, 2

## RT0603BRD072K15L
designator R?  ValueDisplayed: 2.15k  (hidden comment: RT0603BRD072K15L)
RES, 2.15 k, 0.1%, 0.1 W, 0603; Manufacturer: Yageo America; CompType: Resistor; Value: 2.15k; Res_ohm: 2150; Value_Code: 2k15; Tolerance_%: 0.1; Value2: 0.1W; VDC_V: 75; TempCo: 25 ppm/C; SizeArea_mm2: 1.28; SizeX_mm: 1.6; SizeY_mm: 0.8; SizeZ_mm: 1; EIA_Code: E192; U/M: EA; AEC Category: Q200
signal-integrity model Resistor
simulation model Resistor
footprint 0603
footprint 0603M
footprint 0603L
footprint 0603_HV
footprint 0603S
pins: 1, 2

## RT0603BRD072K18L
designator R?  ValueDisplayed: 2.18k  (hidden comment: RT0603BRD072K18L)
RES, 2.18 k, 0.1%, 0.1 W, 0603; Manufacturer: Yageo America; CompType: Resistor; Value: 2.18k; Res_ohm: 2180; Value_Code: 2k18; Tolerance_%: 0.1; Value2: 0.1W; VDC_V: 75; TempCo: 25 ppm/C; SizeArea_mm2: 1.28; SizeX_mm: 1.6; SizeY_mm: 0.8; SizeZ_mm: 1; EIA_Code: E192; U/M: EA; AEC Category: Q200
signal-integrity model Resistor
simulation model Resistor
footprint 0603
footprint 0603M
footprint 0603L
footprint 0603_HV
footprint 0603S
pins: 1, 2

## RT0603BRD072K21L
designator R?  ValueDisplayed: 2.21k  (hidden comment: RT0603BRD072K21L)
RES, 2.21 k, 0.1%, 0.1 W, 0603; Manufacturer: Yageo America; CompType: Resistor; Value: 2.21k; Res_ohm: 2210; Value_Code: 2k21; Tolerance_%: 0.1; Value2: 0.1W; VDC_V: 75; TempCo: 25 ppm/C; SizeArea_mm2: 1.28; SizeX_mm: 1.6; SizeY_mm: 0.8; SizeZ_mm: 1; EIA_Code: E192; U/M: EA; AEC Category: Q200
signal-integrity model Resistor
simulation model Resistor
footprint 0603
footprint 0603M
footprint 0603L
footprint 0603_HV
footprint 0603S
pins: 1, 2

## RT0603BRD072K23L
designator R?  ValueDisplayed: 2.23k  (hidden comment: RT0603BRD072K23L)
RES, 2.23 k, 0.1%, 0.1 W, 0603; Manufacturer: Yageo America; CompType: Resistor; Value: 2.23k; Res_ohm: 2230; Value_Code: 2k23; Tolerance_%: 0.1; Value2: 0.1W; VDC_V: 75; TempCo: 25 ppm/C; SizeArea_mm2: 1.28; SizeX_mm: 1.6; SizeY_mm: 0.8; SizeZ_mm: 1; EIA_Code: E192; U/M: EA; AEC Category: Q200
signal-integrity model Resistor
simulation model Resistor
footprint 0603
footprint 0603M
footprint 0603L
footprint 0603_HV
footprint 0603S
pins: 1, 2

## RT0603BRD072K26L
designator R?  ValueDisplayed: 2.26k  (hidden comment: RT0603BRD072K26L)
RES, 2.26 k, 0.1%, 0.1 W, 0603; Manufacturer: Yageo America; CompType: Resistor; Value: 2.26k; Res_ohm: 2260; Value_Code: 2k26; Tolerance_%: 0.1; Value2: 0.1W; VDC_V: 75; TempCo: 25 ppm/C; SizeArea_mm2: 1.28; SizeX_mm: 1.6; SizeY_mm: 0.8; SizeZ_mm: 1; EIA_Code: E192; U/M: EA; AEC Category: Q200
signal-integrity model Resistor
simulation model Resistor
footprint 0603
footprint 0603M
footprint 0603L
footprint 0603_HV
footprint 0603S
pins: 1, 2

## RT0603BRD072K29L
designator R?  ValueDisplayed: 2.29k  (hidden comment: RT0603BRD072K29L)
RES, 2.29 k, 0.1%, 0.1 W, 0603; Manufacturer: Yageo America; CompType: Resistor; Value: 2.29k; Res_ohm: 2290; Value_Code: 2k29; Tolerance_%: 0.1; Value2: 0.1W; VDC_V: 75; TempCo: 25 ppm/C; SizeArea_mm2: 1.28; SizeX_mm: 1.6; SizeY_mm: 0.8; SizeZ_mm: 1; EIA_Code: E192; U/M: EA; AEC Category: Q200
signal-integrity model Resistor
simulation model Resistor
footprint 0603
footprint 0603M
footprint 0603L
footprint 0603_HV
footprint 0603S
pins: 1, 2

## RT0603BRD072K32L
designator R?  ValueDisplayed: 2.32k  (hidden comment: RT0603BRD072K32L)
RES, 2.32 k, 0.1%, 0.1 W, 0603; Manufacturer: Yageo America; CompType: Resistor; Value: 2.32k; Res_ohm: 2320; Value_Code: 2k32; Tolerance_%: 0.1; Value2: 0.1W; VDC_V: 75; TempCo: 25 ppm/C; SizeArea_mm2: 1.28; SizeX_mm: 1.6; SizeY_mm: 0.8; SizeZ_mm: 1; EIA_Code: E192; U/M: EA; AEC Category: Q200
signal-integrity model Resistor
simulation model Resistor
footprint 0603
footprint 0603M
footprint 0603L
footprint 0603_HV
footprint 0603S
pins: 1, 2

## RT0603BRD072K34L
designator R?  ValueDisplayed: 2.34k  (hidden comment: RT0603BRD072K34L)
RES, 2.34 k, 0.1%, 0.1 W, 0603; Manufacturer: Yageo America; CompType: Resistor; Value: 2.34k; Res_ohm: 2340; Value_Code: 2k34; Tolerance_%: 0.1; Value2: 0.1W; VDC_V: 75; TempCo: 25 ppm/C; SizeArea_mm2: 1.28; SizeX_mm: 1.6; SizeY_mm: 0.8; SizeZ_mm: 1; EIA_Code: E192; U/M: EA; AEC Category: Q200
signal-integrity model Resistor
simulation model Resistor
footprint 0603
footprint 0603M
footprint 0603L
footprint 0603_HV
footprint 0603S
pins: 1, 2

## RT0603BRD072K37L
designator R?  ValueDisplayed: 2.37k  (hidden comment: RT0603BRD072K37L)
RES, 2.37 k, 0.1%, 0.1 W, 0603; Manufacturer: Yageo America; CompType: Resistor; Value: 2.37k; Res_ohm: 2370; Value_Code: 2k37; Tolerance_%: 0.1; Value2: 0.1W; VDC_V: 75; TempCo: 25 ppm/C; SizeArea_mm2: 1.28; SizeX_mm: 1.6; SizeY_mm: 0.8; SizeZ_mm: 1; EIA_Code: E192; U/M: EA; AEC Category: Q200
signal-integrity model Resistor
simulation model Resistor
footprint 0603
footprint 0603M
footprint 0603L
footprint 0603_HV
footprint 0603S
pins: 1, 2

## RT0603BRD072K43L
designator R?  ValueDisplayed: 2.43k  (hidden comment: RT0603BRD072K43L)
RES, 2.43 k, 0.1%, 0.1 W, 0603; Manufacturer: Yageo America; CompType: Resistor; Value: 2.43k; Res_ohm: 2430; Value_Code: 2k43; Tolerance_%: 0.1; Value2: 0.1W; VDC_V: 75; TempCo: 25 ppm/C; SizeArea_mm2: 1.28; SizeX_mm: 1.6; SizeY_mm: 0.8; SizeZ_mm: 1; EIA_Code: E192; U/M: EA; AEC Category: Q200
signal-integrity model Resistor
simulation model Resistor
footprint 0603
footprint 0603M
footprint 0603L
footprint 0603_HV
footprint 0603S
pins: 1, 2

## RT0603BRD072K46L
designator R?  ValueDisplayed: 2.46k  (hidden comment: RT0603BRD072K46L)
RES, 2.46 k, 0.1%, 0.1 W, 0603; Manufacturer: Yageo America; CompType: Resistor; Value: 2.46k; Res_ohm: 2460; Value_Code: 2k46; Tolerance_%: 0.1; Value2: 0.1W; VDC_V: 75; TempCo: 25 ppm/C; SizeArea_mm2: 1.28; SizeX_mm: 1.6; SizeY_mm: 0.8; SizeZ_mm: 1; EIA_Code: E192; U/M: EA; AEC Category: Q200
signal-integrity model Resistor
simulation model Resistor
footprint 0603
footprint 0603M
footprint 0603L
footprint 0603_HV
footprint 0603S
pins: 1, 2

## RT0603BRD072K49L
designator R?  ValueDisplayed: 2.49k  (hidden comment: RT0603BRD072K49L)
RES, 2.49 k, 0.1%, 0.1 W, 0603; Manufacturer: Yageo America; CompType: Resistor; Value: 2.49k; Res_ohm: 2490; Value_Code: 2k49; Tolerance_%: 0.1; Value2: 0.1W; VDC_V: 75; TempCo: 25 ppm/C; SizeArea_mm2: 1.28; SizeX_mm: 1.6; SizeY_mm: 0.8; SizeZ_mm: 1; EIA_Code: E192; U/M: EA; AEC Category: Q200
signal-integrity model Resistor
simulation model Resistor
footprint 0603
footprint 0603M
footprint 0603L
footprint 0603_HV
footprint 0603S
pins: 1, 2

## RT0603BRD072K52L
designator R?  ValueDisplayed: 2.52k  (hidden comment: RT0603BRD072K52L)
RES, 2.52 k, 0.1%, 0.1 W, 0603; Manufacturer: Yageo America; CompType: Resistor; Value: 2.52k; Res_ohm: 2520; Value_Code: 2k52; Tolerance_%: 0.1; Value2: 0.1W; VDC_V: 75; TempCo: 25 ppm/C; SizeArea_mm2: 1.28; SizeX_mm: 1.6; SizeY_mm: 0.8; SizeZ_mm: 1; EIA_Code: E192; U/M: EA; AEC Category: Q200
signal-integrity model Resistor
simulation model Resistor
footprint 0603
footprint 0603M
footprint 0603L
footprint 0603_HV
footprint 0603S
pins: 1, 2

## RT0603BRD072K55L
designator R?  ValueDisplayed: 2.55k  (hidden comment: RT0603BRD072K55L)
RES, 2.55 k, 0.1%, 0.1 W, 0603; Manufacturer: Yageo America; CompType: Resistor; Value: 2.55k; Res_ohm: 2550; Value_Code: 2k55; Tolerance_%: 0.1; Value2: 0.1W; VDC_V: 75; TempCo: 25 ppm/C; SizeArea_mm2: 1.28; SizeX_mm: 1.6; SizeY_mm: 0.8; SizeZ_mm: 1; EIA_Code: E192; U/M: EA; AEC Category: Q200
signal-integrity model Resistor
simulation model Resistor
footprint 0603
footprint 0603M
footprint 0603L
footprint 0603_HV
footprint 0603S
pins: 1, 2

## RT0603BRD072K58L
designator R?  ValueDisplayed: 2.58k  (hidden comment: RT0603BRD072K58L)
RES, 2.58 k, 0.1%, 0.1 W, 0603; Manufacturer: Yageo America; CompType: Resistor; Value: 2.58k; Res_ohm: 2580; Value_Code: 2k58; Tolerance_%: 0.1; Value2: 0.1W; VDC_V: 75; TempCo: 25 ppm/C; SizeArea_mm2: 1.28; SizeX_mm: 1.6; SizeY_mm: 0.8; SizeZ_mm: 1; EIA_Code: E192; U/M: EA; AEC Category: Q200
signal-integrity model Resistor
simulation model Resistor
footprint 0603
footprint 0603M
footprint 0603L
footprint 0603_HV
footprint 0603S
pins: 1, 2

## RT0603BRD072K61L
designator R?  ValueDisplayed: 2.61k  (hidden comment: RT0603BRD072K61L)
RES, 2.61 k, 0.1%, 0.1 W, 0603; Manufacturer: Yageo America; CompType: Resistor; Value: 2.61k; Res_ohm: 2610; Value_Code: 2k61; Tolerance_%: 0.1; Value2: 0.1W; VDC_V: 75; TempCo: 25 ppm/C; SizeArea_mm2: 1.28; SizeX_mm: 1.6; SizeY_mm: 0.8; SizeZ_mm: 1; EIA_Code: E192; U/M: EA; AEC Category: Q200
signal-integrity model Resistor
simulation model Resistor
footprint 0603
footprint 0603M
footprint 0603L
footprint 0603_HV
footprint 0603S
pins: 1, 2

## RT0603BRD072K64L
designator R?  ValueDisplayed: 2.64k  (hidden comment: RT0603BRD072K64L)
RES, 2.64 k, 0.1%, 0.1 W, 0603; Manufacturer: Yageo America; CompType: Resistor; Value: 2.64k; Res_ohm: 2640; Value_Code: 2k64; Tolerance_%: 0.1; Value2: 0.1W; VDC_V: 75; TempCo: 25 ppm/C; SizeArea_mm2: 1.28; SizeX_mm: 1.6; SizeY_mm: 0.8; SizeZ_mm: 1; EIA_Code: E192; U/M: EA; AEC Category: Q200
signal-integrity model Resistor
simulation model Resistor
footprint 0603
footprint 0603M
footprint 0603L
footprint 0603_HV
footprint 0603S
pins: 1, 2

## RT0603BRD072K67L
designator R?  ValueDisplayed: 2.67k  (hidden comment: RT0603BRD072K67L)
RES, 2.67 k, 0.1%, 0.1 W, 0603; Manufacturer: Yageo America; CompType: Resistor; Value: 2.67k; Res_ohm: 2670; Value_Code: 2k67; Tolerance_%: 0.1; Value2: 0.1W; VDC_V: 75; TempCo: 25 ppm/C; SizeArea_mm2: 1.28; SizeX_mm: 1.6; SizeY_mm: 0.8; SizeZ_mm: 1; EIA_Code: E192; U/M: EA; AEC Category: Q200
signal-integrity model Resistor
simulation model Resistor
footprint 0603
footprint 0603M
footprint 0603L
footprint 0603_HV
footprint 0603S
pins: 1, 2

## RT0603BRD072K71L
designator R?  ValueDisplayed: 2.71k  (hidden comment: RT0603BRD072K71L)
RES, 2.71 k, 0.1%, 0.1 W, 0603; Manufacturer: Yageo America; CompType: Resistor; Value: 2.71k; Res_ohm: 2710; Value_Code: 2k71; Tolerance_%: 0.1; Value2: 0.1W; VDC_V: 75; TempCo: 25 ppm/C; SizeArea_mm2: 1.28; SizeX_mm: 1.6; SizeY_mm: 0.8; SizeZ_mm: 1; EIA_Code: E192; U/M: EA; AEC Category: Q200
signal-integrity model Resistor
simulation model Resistor
footprint 0603
footprint 0603M
footprint 0603L
footprint 0603_HV
footprint 0603S
pins: 1, 2

## RT0603BRD072K74L
designator R?  ValueDisplayed: 2.74k  (hidden comment: RT0603BRD072K74L)
RES, 2.74 k, 0.1%, 0.1 W, 0603; Manufacturer: Yageo America; CompType: Resistor; Value: 2.74k; Res_ohm: 2740; Value_Code: 2k74; Tolerance_%: 0.1; Value2: 0.1W; VDC_V: 75; TempCo: 25 ppm/C; SizeArea_mm2: 1.28; SizeX_mm: 1.6; SizeY_mm: 0.8; SizeZ_mm: 1; EIA_Code: E192; U/M: EA; AEC Category: Q200
signal-integrity model Resistor
simulation model Resistor
footprint 0603
footprint 0603M
footprint 0603L
footprint 0603_HV
footprint 0603S
pins: 1, 2

## RT0603BRD072K77L
designator R?  ValueDisplayed: 2.77k  (hidden comment: RT0603BRD072K77L)
RES, 2.77 k, 0.1%, 0.1 W, 0603; Manufacturer: Yageo America; CompType: Resistor; Value: 2.77k; Res_ohm: 2770; Value_Code: 2k77; Tolerance_%: 0.1; Value2: 0.1W; VDC_V: 75; TempCo: 25 ppm/C; SizeArea_mm2: 1.28; SizeX_mm: 1.6; SizeY_mm: 0.8; SizeZ_mm: 1; EIA_Code: E192; U/M: EA; AEC Category: Q200
signal-integrity model Resistor
simulation model Resistor
footprint 0603
footprint 0603M
footprint 0603L
footprint 0603_HV
footprint 0603S
pins: 1, 2

## RT0603BRD072K84L
designator R?  ValueDisplayed: 2.84k  (hidden comment: RT0603BRD072K84L)
RES, 2.84 k, 0.1%, 0.1 W, 0603; Manufacturer: Yageo America; CompType: Resistor; Value: 2.84k; Res_ohm: 2840; Value_Code: 2k84; Tolerance_%: 0.1; Value2: 0.1W; VDC_V: 75; TempCo: 25 ppm/C; SizeArea_mm2: 1.28; SizeX_mm: 1.6; SizeY_mm: 0.8; SizeZ_mm: 1; EIA_Code: E192; U/M: EA; AEC Category: Q200
signal-integrity model Resistor
simulation model Resistor
footprint 0603
footprint 0603M
footprint 0603L
footprint 0603_HV
footprint 0603S
pins: 1, 2

## RT0603BRD072K87L
designator R?  ValueDisplayed: 2.87k  (hidden comment: RT0603BRD072K87L)
RES, 2.87 k, 0.1%, 0.1 W, 0603; Manufacturer: Yageo America; CompType: Resistor; Value: 2.87k; Res_ohm: 2870; Value_Code: 2k87; Tolerance_%: 0.1; Value2: 0.1W; VDC_V: 75; TempCo: 25 ppm/C; SizeArea_mm2: 1.28; SizeX_mm: 1.6; SizeY_mm: 0.8; SizeZ_mm: 1; EIA_Code: E192; U/M: EA; AEC Category: Q200
signal-integrity model Resistor
simulation model Resistor
footprint 0603
footprint 0603M
footprint 0603L
footprint 0603_HV
footprint 0603S
pins: 1, 2

## RT0603BRD072K91L
designator R?  ValueDisplayed: 2.91k  (hidden comment: RT0603BRD072K91L)
RES, 2.91 k, 0.1%, 0.1 W, 0603; Manufacturer: Yageo America; CompType: Resistor; Value: 2.91k; Res_ohm: 2910; Value_Code: 2k91; Tolerance_%: 0.1; Value2: 0.1W; VDC_V: 75; TempCo: 25 ppm/C; SizeArea_mm2: 1.28; SizeX_mm: 1.6; SizeY_mm: 0.8; SizeZ_mm: 1; EIA_Code: E192; U/M: EA; AEC Category: Q200
signal-integrity model Resistor
simulation model Resistor
footprint 0603
footprint 0603M
footprint 0603L
footprint 0603_HV
footprint 0603S
pins: 1, 2

## RT0603BRD072K94L
designator R?  ValueDisplayed: 2.94k  (hidden comment: RT0603BRD072K94L)
RES, 2.94 k, 0.1%, 0.1 W, 0603; Manufacturer: Yageo America; CompType: Resistor; Value: 2.94k; Res_ohm: 2940; Value_Code: 2k94; Tolerance_%: 0.1; Value2: 0.1W; VDC_V: 75; TempCo: 25 ppm/C; SizeArea_mm2: 1.28; SizeX_mm: 1.6; SizeY_mm: 0.8; SizeZ_mm: 1; EIA_Code: E192; U/M: EA; AEC Category: Q200
signal-integrity model Resistor
simulation model Resistor
footprint 0603
footprint 0603M
footprint 0603L
footprint 0603_HV
footprint 0603S
pins: 1, 2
